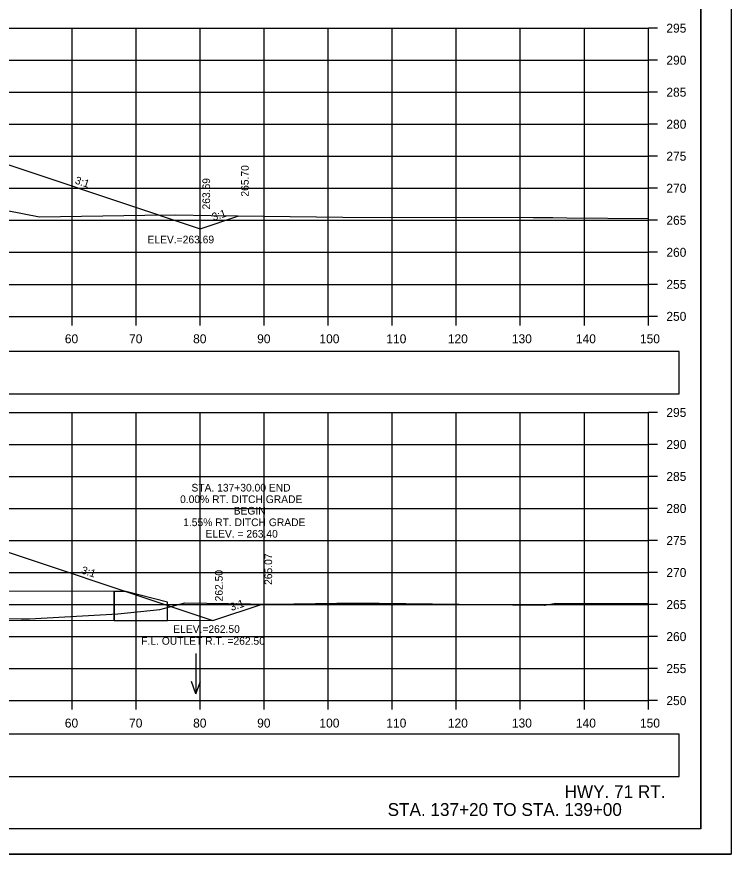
# Model space of a CAD drawing. Extents: x 285 to 4233, y -659 to 3710.
# Drawn here: x 2610.9 to 2722.4, y 2322.9 to 2453.7 of the extents above; entities that cross this region are included whole.
import ezdxf

# ---------------------------------------------------------------- set-up
doc = ezdxf.new("R2010")
doc.units = 0
for name, color, linetype in [('R_Axis', 7, 'Continuous'), ('R_Axis Annot', 7, 'Continuous'), ('R_Border', 7, 'Continuous'), ('R_Draft', 7, 'Continuous'), ('R_Exist Surface', 7, 'Continuous'), ('R_Fin Surface', 7, 'Continuous'), ('R_Grid', 7, 'Continuous'), ('R_No Plot', 7, 'Continuous'), ('R_Water', 7, 'Continuous'), ('R_Water Annot', 7, 'Continuous'), ('R_Xsect Elev', 7, 'Continuous'), ('R_Xsect Slope', 7, 'Continuous')]:
    doc.layers.add(name, color=color, linetype=linetype)

msp = doc.modelspace()

# ---------------------------------------------------------------- linework, layer by layer
at = {"layer": 'R_Axis'}
for p, q in [((2709.5, 2406.87), (2709.5, 2451.87)), ((2710.9, 2451.87), (2709.5, 2451.87)), ((2710.9, 2446.87), (2709.5, 2446.87)), ((2710.9, 2441.87), (2709.5, 2441.87)), ((2710.9, 2436.87), (2709.5, 2436.87)), ((2710.9, 2431.87), (2709.5, 2431.87)), ((2710.9, 2426.87), (2709.5, 2426.87)), ((2710.9, 2421.87), (2709.5, 2421.87)), ((2710.9, 2416.87), (2709.5, 2416.87)), ((2710.9, 2411.87), (2709.5, 2411.87)), ((2409.5, 2406.87), (2709.5, 2406.87)), ((2619.5, 2405.47), (2619.5, 2406.87)), ((2629.5, 2405.47), (2629.5, 2406.87)), ((2639.5, 2405.47), (2639.5, 2406.87)), ((2649.5, 2405.47), (2649.5, 2406.87)), ((2659.5, 2405.47), (2659.5, 2406.87)), ((2669.5, 2405.47), (2669.5, 2406.87)), ((2679.5, 2405.47), (2679.5, 2406.87)), ((2689.5, 2405.47), (2689.5, 2406.87)), ((2699.5, 2405.47), (2699.5, 2406.87)), ((2709.5, 2405.47), (2709.5, 2406.87)), ((2710.9, 2406.87), (2709.5, 2406.87)), ((2709.5, 2346.87), (2709.5, 2391.87)), ((2710.9, 2391.87), (2709.5, 2391.87)), ((2710.9, 2386.87), (2709.5, 2386.87)), ((2710.9, 2381.87), (2709.5, 2381.87)), ((2710.9, 2376.87), (2709.5, 2376.87)), ((2710.9, 2371.87), (2709.5, 2371.87)), ((2710.9, 2366.87), (2709.5, 2366.87)), ((2710.9, 2361.87), (2709.5, 2361.87)), ((2710.9, 2356.87), (2709.5, 2356.87)), ((2710.9, 2351.87), (2709.5, 2351.87)), ((2409.5, 2346.87), (2709.5, 2346.87)), ((2619.5, 2345.47), (2619.5, 2346.87)), ((2629.5, 2345.47), (2629.5, 2346.87)), ((2639.5, 2345.47), (2639.5, 2346.87)), ((2649.5, 2345.47), (2649.5, 2346.87)), ((2659.5, 2345.47), (2659.5, 2346.87)), ((2669.5, 2345.47), (2669.5, 2346.87)), ((2679.5, 2345.47), (2679.5, 2346.87)), ((2689.5, 2345.47), (2689.5, 2346.87)), ((2699.5, 2345.47), (2699.5, 2346.87)), ((2709.5, 2345.47), (2709.5, 2346.87)), ((2710.9, 2346.87), (2709.5, 2346.87))]:
    msp.add_line(p, q, dxfattribs=at)
at = {"layer": 'R_Axis Annot'}
for points in [[(2573.96, 2394.76), (2714.32, 2394.76), (2714.32, 2401.41), (2573.96, 2401.41)], [(2573.96, 2335.01), (2714.32, 2335.01), (2714.32, 2341.66), (2573.96, 2341.66)]]:
    msp.add_lwpolyline(points, close=True, dxfattribs=at)
at = {"layer": 'R_Border'}
for q in [(2717.68, 2532.33), (2401.5, 2326.87)]:
    msp.add_line((2717.68, 2326.87), q, dxfattribs=at)
at = {"layer": 'R_Exist Surface'}
for points in [[(2596.81, 2425.85), (2614.43, 2422.42), (2630.88, 2422.65), (2635.66, 2422.7), (2641.24, 2422.63), (2661.81, 2422.35), (2691.53, 2422.3), (2694.56, 2422.29), (2696.74, 2422.27), (2709.5, 2422.16)], [(2603.87, 2359.68), (2611.58, 2359.65), (2612.5, 2359.66), (2612.56, 2359.66), (2612.86, 2359.67), (2626.68, 2360.43), (2633.2, 2361.09), (2637.1, 2362.12), (2650.79, 2361.92), (2660.85, 2362.1), (2665.99, 2362.07), (2667.44, 2362.09), (2688.26, 2361.83), (2693.27, 2361.77), (2693.34, 2361.8), (2695.03, 2362.1), (2709.5, 2362.02)]]:
    msp.add_lwpolyline(points, dxfattribs=at)
at = {"layer": 'R_Fin Surface'}
for points in [[(2477.4, 2422.54), (2482.32, 2420.9), (2517.5, 2432.63), (2541.5, 2436.63), (2547.5, 2436.87), (2571.5, 2436.65), (2573.5, 2436.63), (2581.5, 2436.56), (2601.5, 2433.23), (2639.51, 2420.56), (2645.54, 2422.57)], [(2478.47, 2359.62), (2517.5, 2372.63), (2541.5, 2376.63), (2547.5, 2376.87), (2571.5, 2376.39), (2573.5, 2376.35), (2581.5, 2376.03), (2601.5, 2372.7), (2641.48, 2359.37), (2649.2, 2361.94)]]:
    msp.add_lwpolyline(points, dxfattribs=at)
at = {"layer": 'R_Grid'}
for p, q in [((2409.5, 2451.87), (2709.5, 2451.87)), ((2619.5, 2406.87), (2619.5, 2451.87)), ((2629.5, 2406.87), (2629.5, 2451.87)), ((2639.5, 2406.87), (2639.5, 2451.87)), ((2649.5, 2406.87), (2649.5, 2451.87)), ((2659.5, 2406.87), (2659.5, 2451.87)), ((2669.5, 2406.87), (2669.5, 2451.87)), ((2679.5, 2406.87), (2679.5, 2451.87)), ((2689.5, 2406.87), (2689.5, 2451.87)), ((2699.5, 2406.87), (2699.5, 2451.87)), ((2709.5, 2406.87), (2709.5, 2451.87)), ((2409.5, 2446.87), (2709.5, 2446.87)), ((2409.5, 2441.87), (2709.5, 2441.87)), ((2409.5, 2436.87), (2709.5, 2436.87)), ((2409.5, 2431.87), (2709.5, 2431.87)), ((2409.5, 2426.87), (2709.5, 2426.87)), ((2409.5, 2421.87), (2709.5, 2421.87)), ((2409.5, 2416.87), (2709.5, 2416.87)), ((2409.5, 2411.87), (2709.5, 2411.87)), ((2409.5, 2406.87), (2709.5, 2406.87)), ((2409.5, 2391.87), (2709.5, 2391.87)), ((2619.5, 2346.87), (2619.5, 2391.87)), ((2629.5, 2346.87), (2629.5, 2391.87)), ((2639.5, 2346.87), (2639.5, 2391.87)), ((2649.5, 2346.87), (2649.5, 2391.87)), ((2659.5, 2346.87), (2659.5, 2391.87)), ((2669.5, 2346.87), (2669.5, 2391.87)), ((2679.5, 2346.87), (2679.5, 2391.87)), ((2689.5, 2346.87), (2689.5, 2391.87)), ((2699.5, 2346.87), (2699.5, 2391.87)), ((2709.5, 2346.87), (2709.5, 2391.87)), ((2409.5, 2386.87), (2709.5, 2386.87)), ((2409.5, 2381.87), (2709.5, 2381.87)), ((2409.5, 2376.87), (2709.5, 2376.87)), ((2409.5, 2371.87), (2709.5, 2371.87)), ((2409.5, 2366.87), (2709.5, 2366.87)), ((2409.5, 2361.87), (2709.5, 2361.87)), ((2409.5, 2356.87), (2709.5, 2356.87)), ((2409.5, 2351.87), (2709.5, 2351.87)), ((2409.5, 2346.87), (2709.5, 2346.87))]:
    msp.add_line(p, q, dxfattribs=at)
at = {"layer": 'R_No Plot'}
msp.add_line((2389.1, 2322.89), (2722.43, 2322.89), dxfattribs=at)
for points in [[(2389.09, 2536.23), (2722.43, 2536.23), (2722.43, 2322.89), (2389.09, 2322.89)], [(2635.42, 2532.33), (2655.04, 2532.33), (2655.04, 2522.45), (2671.15, 2522.45), (2694.35, 2522.45), (2694.47, 2494.29), (2717.68, 2494.29), (2717.68, 2326.87), (2401.5, 2326.87), (2401.5, 2532.33)]]:
    msp.add_lwpolyline(points, close=True, dxfattribs=at)
at = {"layer": 'R_Water'}
msp.add_line((2478.47, 2359.62), (2641.48, 2359.37), dxfattribs=at)
for points in [[(2493.74, 2359.6), (2626.08, 2359.39), (2626.09, 2363.89), (2493.74, 2364.1)], [(2626.09, 2363.89), (2626.08, 2359.39), (2634.41, 2359.38), (2634.42, 2362.26), (2627.92, 2363.89)]]:
    msp.add_lwpolyline(points, close=True, dxfattribs=at)
at = {"layer": 'R_Water Annot'}
for p, q in [((2638.85, 2354.24), (2638.85, 2347.96)), ((2638.85, 2347.96), (2638.15, 2349.88)), ((2638.85, 2347.96), (2639.55, 2349.88))]:
    msp.add_line(p, q, dxfattribs=at)

# ---------------------------------------------------------------- texts
at = {"layer": 'R_Axis Annot'}
for s, p in [('295', (2712.3, 2451.17)), ('290', (2712.3, 2446.17)), ('285', (2712.3, 2441.17)), ('280', (2712.3, 2436.17)), ('275', (2712.3, 2431.17)), ('270', (2712.3, 2426.17)), ('265', (2712.3, 2421.17)), ('260', (2712.3, 2416.17)), ('255', (2712.3, 2411.17)), ('250', (2712.3, 2406.17)), ('60', (2618.38, 2402.67)), ('70', (2628.41, 2402.67)), ('80', (2638.41, 2402.67)), ('90', (2648.41, 2402.67)), ('100', (2658.13, 2402.67)), ('110', (2668.58, 2402.67)), ('120', (2678.18, 2402.67)), ('130', (2688.18, 2402.67)), ('140', (2698.18, 2402.67)), ('150', (2708.18, 2402.67)), ('295', (2712.3, 2391.17)), ('290', (2712.3, 2386.17)), ('285', (2712.3, 2381.17)), ('280', (2712.3, 2376.17)), ('275', (2712.3, 2371.17)), ('270', (2712.3, 2366.17)), ('265', (2712.3, 2361.17)), ('260', (2712.3, 2356.17)), ('255', (2712.3, 2351.17)), ('250', (2712.3, 2346.17)), ('60', (2618.38, 2342.67)), ('70', (2628.41, 2342.67)), ('80', (2638.41, 2342.67)), ('90', (2648.41, 2342.67)), ('100', (2658.13, 2342.67)), ('110', (2668.58, 2342.67)), ('120', (2678.18, 2342.67)), ('130', (2688.18, 2342.67)), ('140', (2698.18, 2342.67)), ('150', (2708.18, 2342.67))]:
    msp.add_text(s, height=1.4, dxfattribs=at).set_placement(p)
at = {"layer": 'R_Draft'}
for s, p in [('HWY. 71 RT. ', (2696.41, 2331.66)), ('STA. 137+20 TO STA. 139+00', (2668.78, 2328.87))]:
    msp.add_text(s, height=2, dxfattribs=at).set_placement(p)
at = {"layer": 'R_Water Annot'}
msp.add_text('F.L. OUTLET R.T. =262.50', height=1.2, dxfattribs=at).set_placement((2630.31, 2355.6))
at = {"layer": 'R_Xsect Elev'}
for s, p in [('265.70', (2647.09, 2425.57)), ('263.69', (2641.06, 2423.56)), ('265.07', (2650.75, 2364.94)), ('262.50', (2643.03, 2362.37))]:
    msp.add_text(s, height=1.2, rotation=90, dxfattribs=at).set_placement(p)
for s, p in [('ELEV.=263.69', (2631.29, 2418.27)), ('STA. 137+30.00 END', (2638.15, 2379.52)), ('0.00% RT. DITCH GRADE', (2636.38, 2377.72)), ('BEGIN', (2644.75, 2375.92)), ('1.55% RT. DITCH GRADE', (2636.86, 2374.12)), ('ELEV. = 263.40', (2640.35, 2372.32)), ('ELEV.=262.50', (2635.31, 2357.44))]:
    msp.add_text(s, height=1.2, dxfattribs=at).set_placement(p)
at = {"layer": 'R_Xsect Slope'}
for rotation, p in [(341.5651, (2619.87, 2427.63)), (18.4349, (2641.58, 2421.78)), (341.5651, (2620.86, 2366.77)), (18.4349, (2644.39, 2360.87))]:
    msp.add_text('3:1', height=1.2, rotation=rotation, dxfattribs=at).set_placement(p)

doc.saveas('drawing.dxf')
